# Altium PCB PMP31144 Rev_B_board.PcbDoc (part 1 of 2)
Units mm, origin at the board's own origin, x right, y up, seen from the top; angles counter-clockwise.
Board outline 104.14 x 73.15 mm, 4 copper layers (Top Layer, Layer 1, Layer 2, Bottom Layer), stack 1.787 mm thick; 110 components, 51 nets, 277 pads, 139 vias.
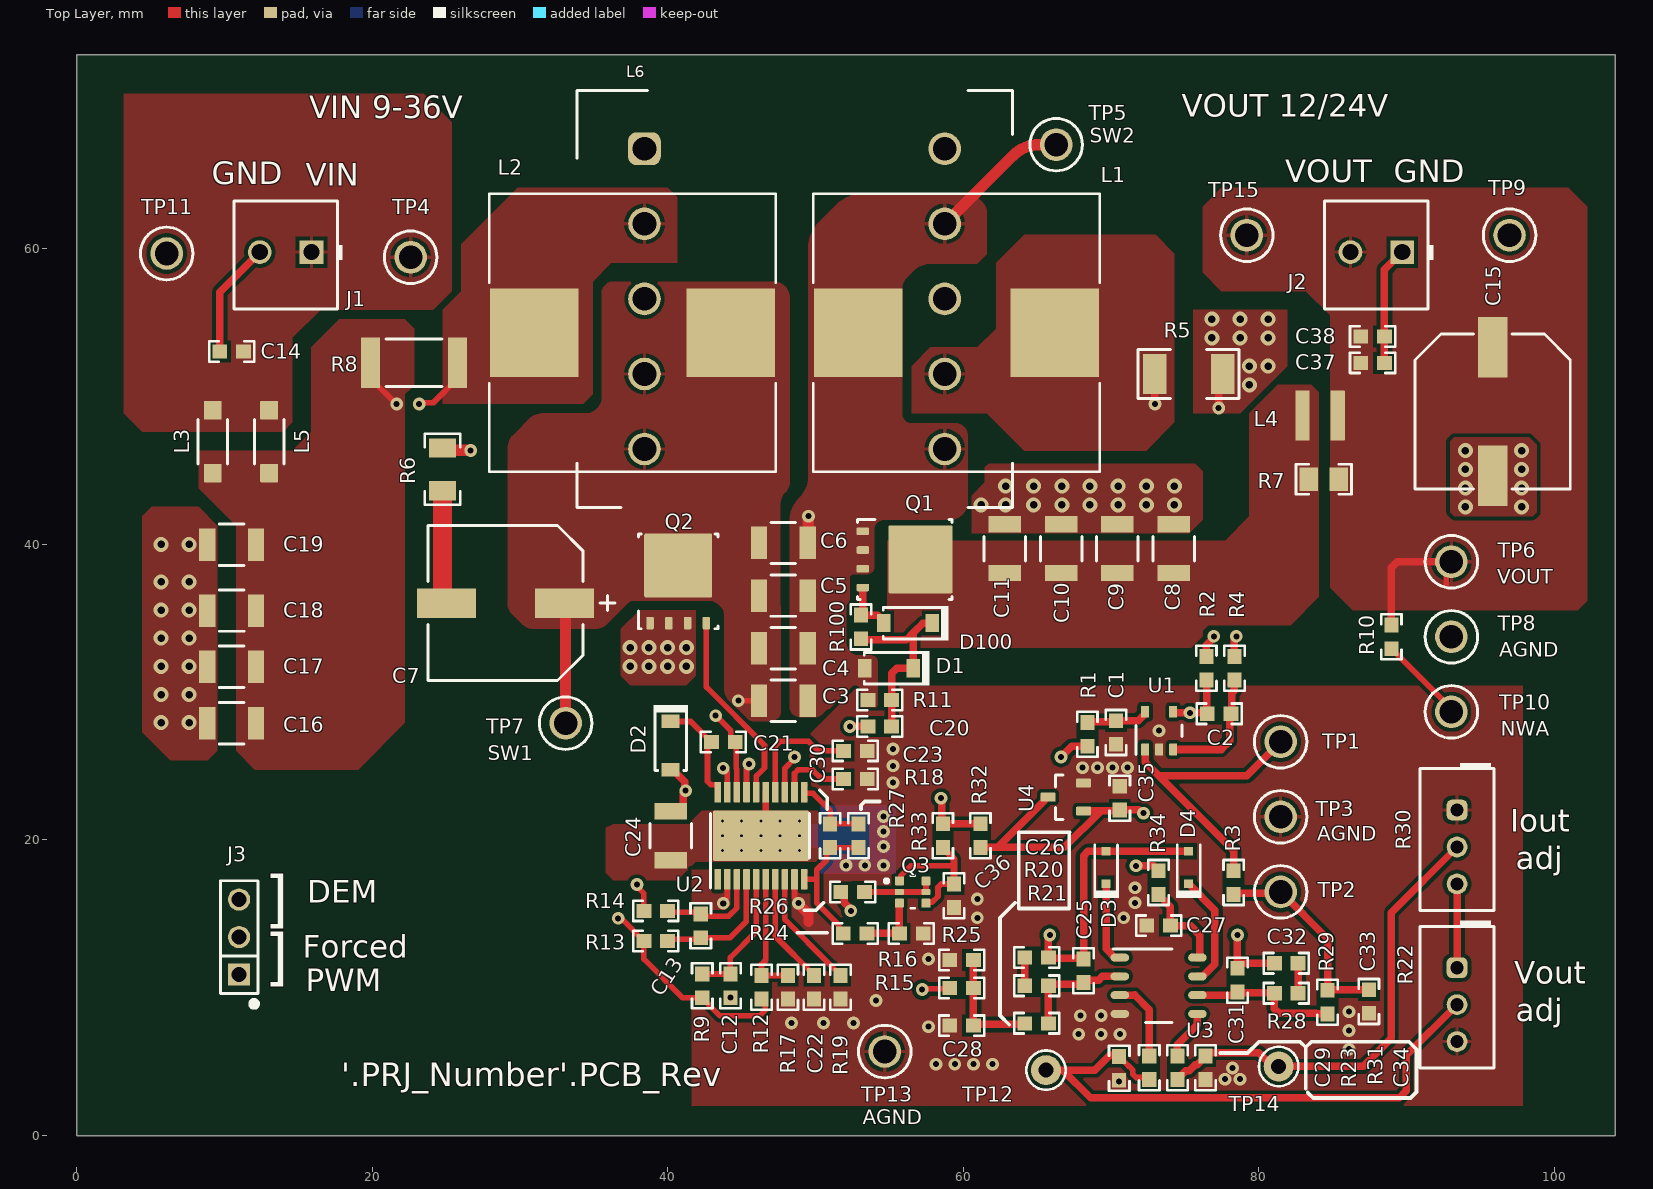
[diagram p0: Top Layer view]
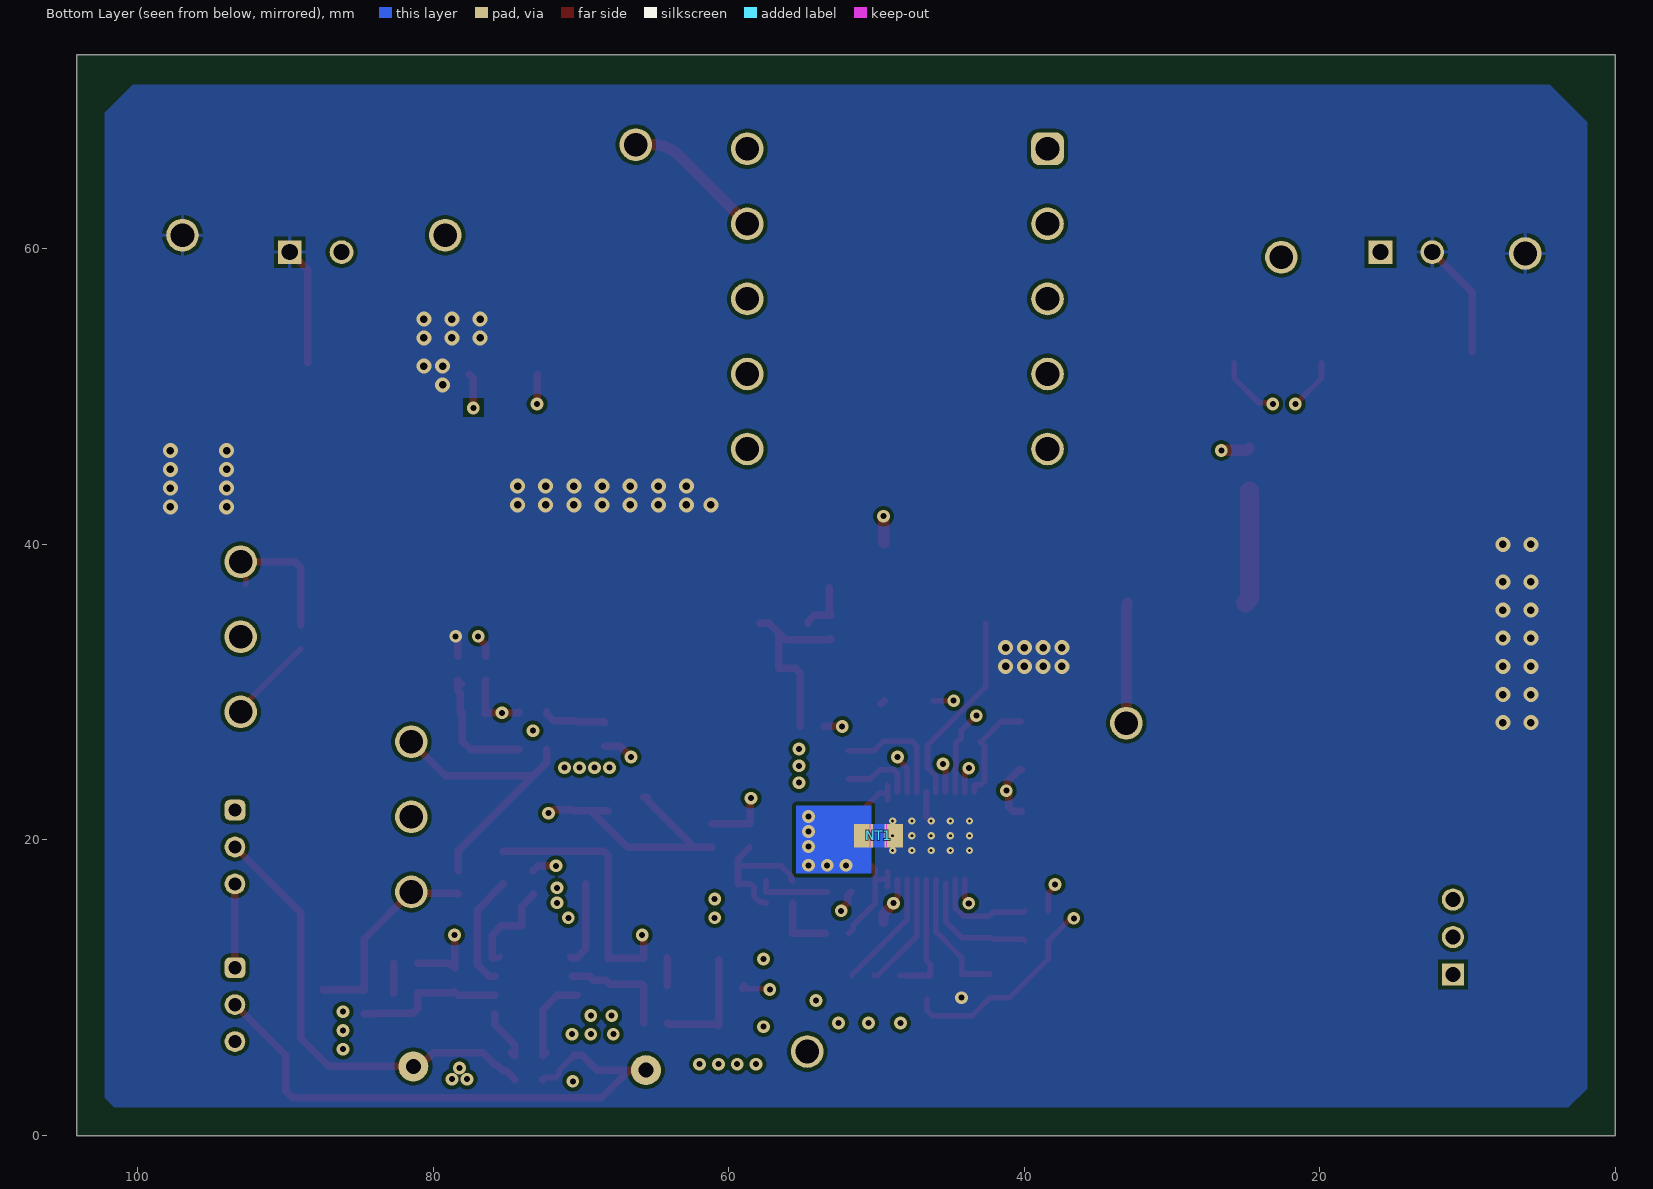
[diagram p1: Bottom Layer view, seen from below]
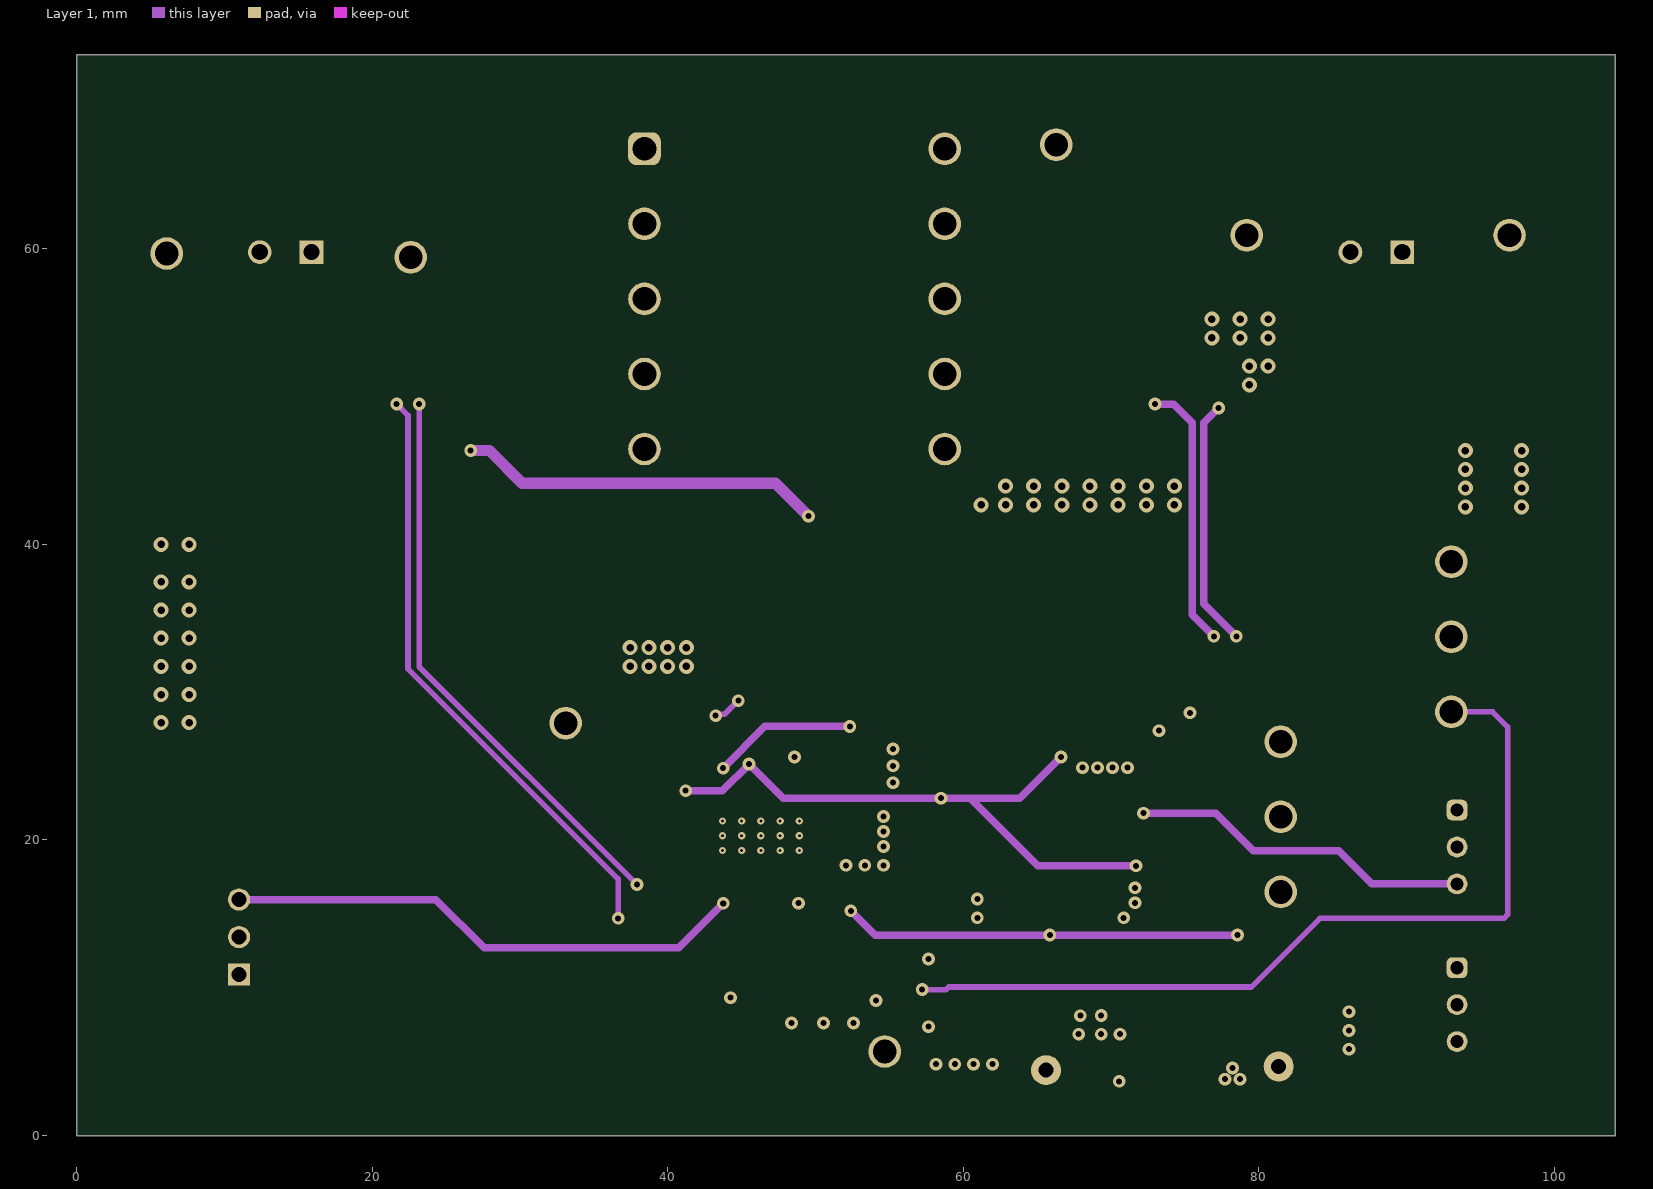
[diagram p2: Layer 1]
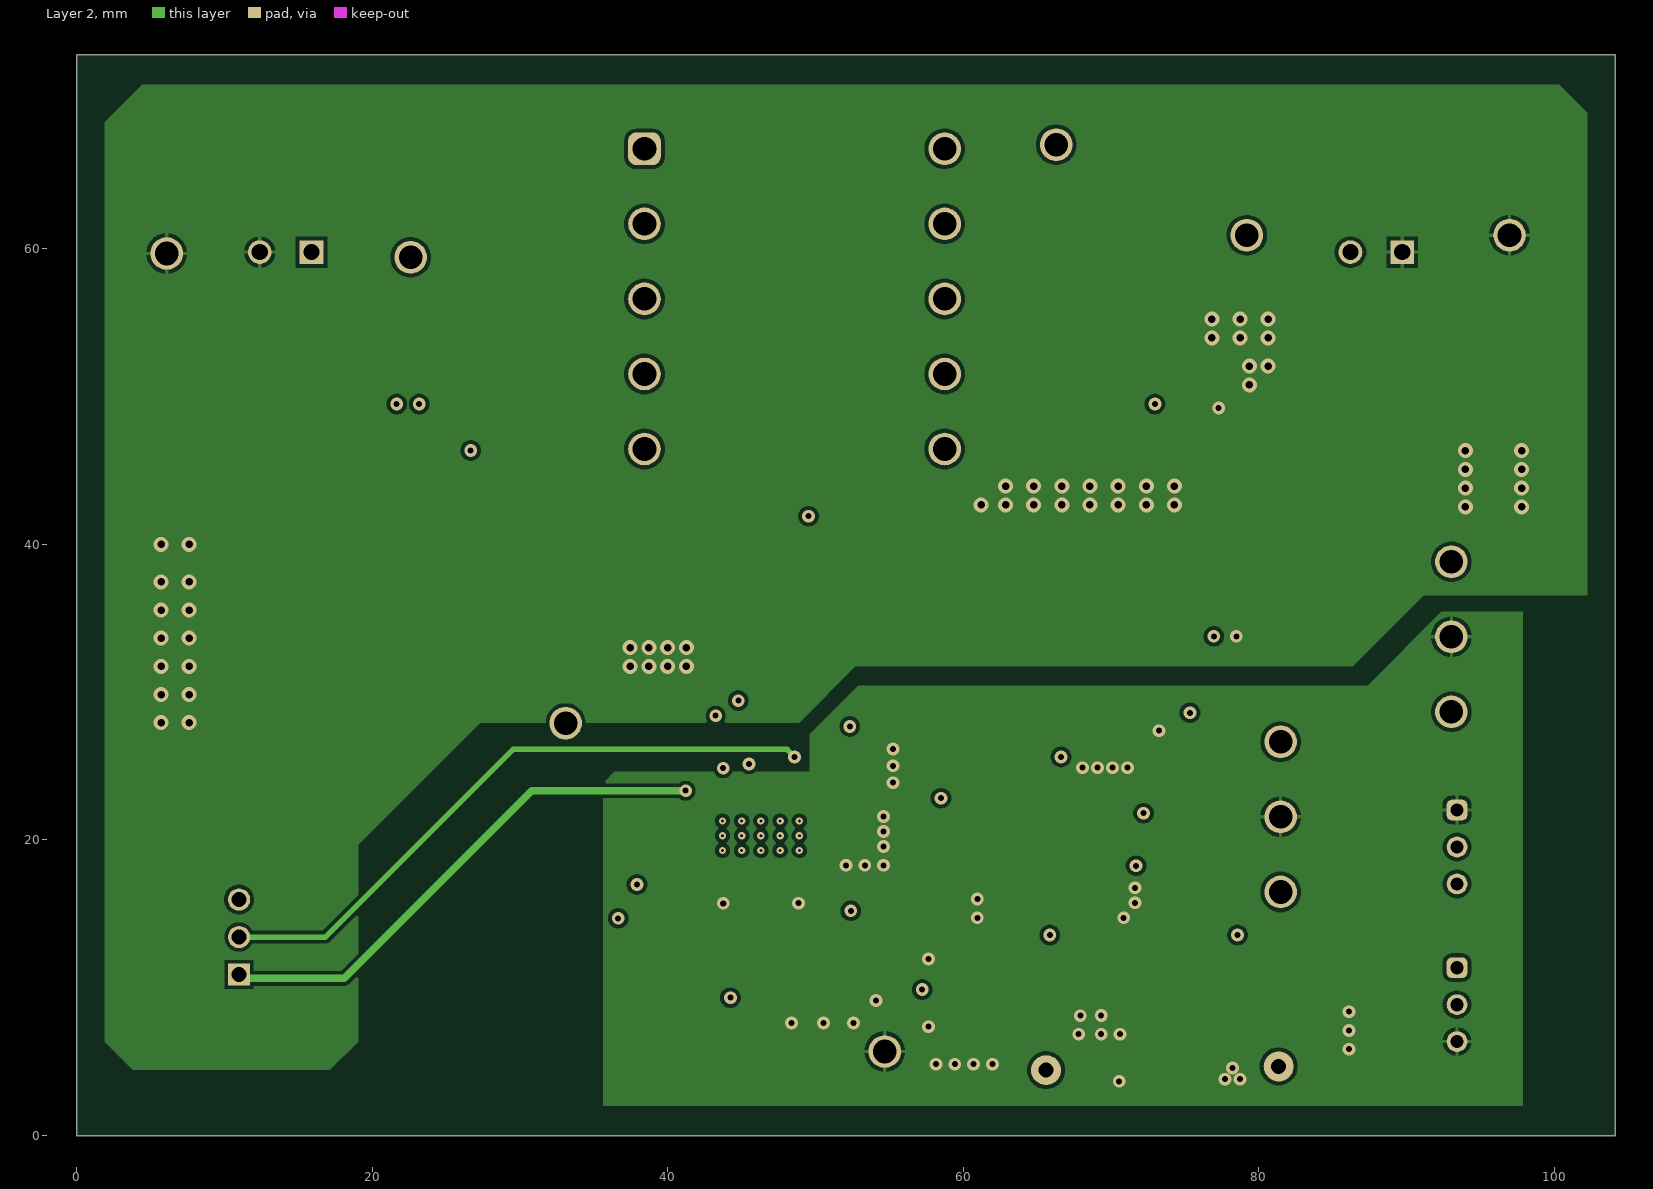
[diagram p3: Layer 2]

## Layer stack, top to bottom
Top Solder: solder mask 0.0102, Solder Resist, Dk 3.5
Top Layer: signal copper 0.0356
Dielectric 1: prepreg 0.0711, PP-006, Dk 4.1
Layer 1: signal copper 0.035
Dielectric1: core 1.5037, FR-4, Dk 4.8
Layer 2: signal copper 0.035
Dielectric 2: prepreg 0.0711, PP-006, Dk 4.1
Bottom Layer: signal copper 0.0356
Bottom Solder: solder mask 0.0102, Solder Resist, Dk 3.5

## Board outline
0,0 0,73.152 104.14,73.152 104.14,0

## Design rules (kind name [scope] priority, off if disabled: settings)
AcuteAngle [All] p1: minimum=4.50000000000000E+0001 checktracksonly=FALSE
AssemblyTestPointUsage [All] p1: valid=2
BoardOutlineClearance BoardOutlineClearance_MountingHoles [OnCopper and InComponentClass('Mounting Holes')] p1: gap=1.016 ignorepadtopadclearanceinfootprint=FALSE
BoardOutlineClearance BoardOutlineClearance_Poly [OnCopper and IsPoly] p2: gap=0.635 ignorepadtopadclearanceinfootprint=FALSE
BoardOutlineClearance [OnCopper and Not InComponentClass('Logo') and not InComponentClass('FiducialMark') and not InRegion(1000,500,4000,800) and not InPoly] p3: gap=1.905 ignorepadtopadclearanceinfootprint=FALSE
Clearance Clearance_1 [InComponent('NT1')] p1: gap=0 ignorepadtopadclearanceinfootprint=FALSE
Clearance Clearance_Keepouts [((IsTrack Or IsArc) And Not InPoly) And IsFree and IsKeepOut vs ((IsTrack Or IsArc) And Not InPoly) And IsFree and IsKeepOut] p2: gap=0 ignorepadtopadclearanceinfootprint=FALSE
Clearance Clearance_Poly [InPolygon] p3: gap=0.254 ignorepadtopadclearanceinfootprint=FALSE
Clearance Clearance_FiducialMark [IsKeepOut and InComponentClass('FiducialMark') vs IsPad and InComponentClass('FiducialMark')] p4: gap=0 ignorepadtopadclearanceinfootprint=FALSE
Clearance Clearance_U2 [InComponent('U2')] p5: gap=0.254 ignorepadtopadclearanceinfootprint=FALSE except(0.2: Arc-SMDPad Track-SMDPad SMDPad-SMDPad)
Clearance [All] p6: gap=0.254 ignorepadtopadclearanceinfootprint=FALSE
ComponentClearance ComponentClearance_MountingHoles_FiducialMarks [InComponentClass('Mounting Holes') vs InComponentClass('FiducialMark')] p1: gap=1.27 collisioncheckmode=3 verticalgap=0.254 showdistances=FALSE
ComponentClearance ComponentClearance_Shunt [InComponentClass('Header') vs InComponentClass('Shunt')] p2: gap=0 collisioncheckmode=3 verticalgap=0 showdistances=FALSE
ComponentClearance ComponentClearance_Logo [InComponentClass('Logo')] p3: gap=1.27 collisioncheckmode=3 verticalgap=0.254 showdistances=FALSE
ComponentClearance ComponentClearance_ScrewToNut [(HasFootprint('NY PMS 440 0025 PH')) vs (HasFootprint('Keystone_1902C'))] p4: gap=0.127 collisioncheckmode=3 verticalgap=0.254 showdistances=FALSE
ComponentClearance ComponentClearance_MountingHoles [InComponentClass('Mounting Holes')] p5: gap=6.35 collisioncheckmode=3 verticalgap=2540 showdistances=FALSE
ComponentClearance ComponentClearance_SmallPassives [HasFootprint('0201*') or HasFootprint('0402*') or HasFootprint('0508') or HasFootprint('0603*') or HasFootprint('0612') or HasFootprint('0805*') or HasFootprint('0815*') or HasFootprint('0830*') or HasFootprint('1206*') or HasFootprint('1210*') or HasFootprint('1808*') or HasFootprint('1812*') or HasFootprint('1825*') or HasFootprint('2010*') or HasFootprint('2220*') or HasFootprint('2225*') or HasFootprint('2512*') or HasFootprint('2728*') or HasFootprint('3518*') vs HasFootprint('0201*') or HasFootprint('0402*') or HasFootprint('0508') or HasFootprint('0603*') or HasFootprint('0612') or HasFootprint('0805*') or HasFootprint('0815*') or HasFootprint('0830*') or HasFootprint('1206*') or HasFootprint('1210*') or HasFootprint('1808*') or HasFootprint('1812*') or HasFootprint('1825*') or HasFootprint('2010*') or HasFootprint('2220*') or HasFootprint('2225*') or HasFootprint('2512*') or HasFootprint('2728*') or HasFootprint('3518*')] p6: gap=0.38 collisioncheckmode=3 verticalgap=0.254 showdistances=FALSE
ComponentClearance ComponentClearance_1 [InComponent('L1')or InComponent('L2') vs InComponent('L6')] p7: gap=0 collisioncheckmode=3 verticalgap=0 showdistances=FALSE
ComponentClearance ComponentClearance_THtoSMT [IsThruComponent vs IsSMTComponent] p8: gap=1.016 collisioncheckmode=3 verticalgap=0.762 showdistances=FALSE
ComponentClearance ComponentClearance_THtoTH [IsThruComponent vs IsThruComponent] p9: gap=0.762 collisioncheckmode=3 verticalgap=0.762 showdistances=FALSE
ComponentClearance [All] p10: gap=0.762 collisioncheckmode=3 verticalgap=0.254 showdistances=FALSE
DiffPairsRouting [All] p1: maxlimit=2.54 minlimit=0.254 mostfreqgap=0.254 toplayer_minwidth=0.381 toplayer_maxwidth=0.381 toplayer_prefwidth=0.381 midlayer1_minwidth=0.381 midlayer1_maxwidth=0.381 midlayer1_prefwidth=0.381 midlayer2_minwidth=0.381 midlayer2_maxwidth=0.381 midlayer2_prefwidth=0.381 bottomlayer_minwidth=0.381 bottomlayer_maxwidth=0.381 bottomlayer_prefwidth=0.381 maxuncoupledlength=25.4
FabricationTestPointUsage TestPointUsage [All] p1: valid=2 allowmultiple=FALSE
FabricationTestpoint Testpoint [All] p1: side=3 testpointundercomponent=TRUE minsize=1.016 maxsize=2.54 preferedsize=1.524 minholesize=0 maxholesize=1.016 preferedholesize=0.813 testpointgrid=0.025 allowsidetop=TRUE allowsidebottom=TRUE usegrid=TRUE gridtolerance=0
FanoutControl Fanout_LCC [IsLCC] p1: bgadir=Out bgaviamode=Centered fanoutstyle=Auto fanoutdirection=Alternating viagrid=0.025 // Fanout_LCC (Default Rule)
FanoutControl Fanout_BGA [IsBGA] p2: bgadir=Out bgaviamode=Centered fanoutstyle=Auto fanoutdirection=Alternating viagrid=0.025 // Fanout_BGA (Default Rule)
FanoutControl Fanout_Default [All] p4: bgadir=Out bgaviamode=Centered fanoutstyle=Auto fanoutdirection=Alternating viagrid=0.025 // Fanout_Default (Default Rule)
FanoutControl Fanout_Small [(CompPinCount < 5)] p5: bgadir=Out bgaviamode=Centered fanoutstyle=Auto fanoutdirection=OutThenIn viagrid=0.025 // Fanout_Small (Default Rule)
HoleSize [All] p1: absolutevalues=TRUE maxlimit=6.375 minlimit=0.2 maxpercent=80.000 minpercent=20.000
MinimumAnnularRing MinimumAnnularRing_ThermalPadVias [IsVia and InAnyComponent] p1: minimumring=0.15
MinimumAnnularRing [All] p2: minimumring=0.203
MinimumSolderMaskSliver MinimumSolderMaskSliver_Logo [InComponentClass('Logo') vs InComponentClass('Logo')] p1: minsoldermaskwidth=0.018
MinimumSolderMaskSliver [All] p2: minsoldermaskwidth=0.1
PlaneConnect [All] p1: planeconnectstyle=Relief reliefexpansion=0.254 reliefentries=4 reliefconductorwidth=0.254 reliefairgap=0.254
PolygonConnect [All] p1: thpad.connectstyle=Relief thpad.reliefconductorwidth=0.254 thpad.reliefentries=4 thpad.polygonreliefangle="90 Angle" thpad.airgapwidth=0.254 smdpad.connectstyle=Direct smdpad.reliefconductorwidth=0.254 smdpad.reliefentries=4 smdpad.polygonreliefangle="90 Angle" smdpad.airgapwidth=0.254 via.connectstyle=Direct via.reliefconductorwidth=0.254 via.reliefentries=4 via.polygonreliefangle="90 Angle" via.airgapwidth=0.254
RoutingVias ThermalPadVias [IsVia and InAnyComponent] p1: holewidth=0.2 width=0.5 viastyle="Through Hole" minholewidth=0.2 minwidth=0.5 maxholewidth=0.33 maxwidth=0.6
RoutingVias [All] p2: holewidth=0.406 width=0.864 viastyle="Through Hole" minholewidth=0.2 minwidth=0.66 maxholewidth=1.016 maxwidth=1.651
SilkToBoardRegionClearance [Not ((IsComment or IsDesignator) And (Hide <> 'False')) and not InRegion(1000,500,4000,800)] p1:
SilkToSilkClearance SilkToSilkClearance_Pb-FreeLogo [(HasFootprint('Pb-Free_Overlay_Medium') OR HasFootprint('Pb-Free_Overlay_Small')) vs (HasFootprint('Pb-Free_Overlay_Medium') OR HasFootprint('Pb-Free_Overlay_Small'))] p1: silktosilkclearance=0
SilkToSilkClearance [All] p2: silktosilkclearance=0.102
SilkToSolderMaskClearance SilkToComponentPadClearance [(IsPad or IsFill or IsRegion) and InAnycomponent] p1: minsilkscreentomaskgap=0.127 clearancetoexposedcopper=TRUE
SilkToSolderMaskClearance "Silk to Solder Mask Opening" [All] p2: minsilkscreentomaskgap=0.102 clearancetoexposedcopper=FALSE
SolderMaskExpansion [All] p1: expansion=0.05 istentingtop=FALSE
Width [All] p1: maxlimit=2.54 minlimit=0.152 preferedwidth=0.254 checkconnectedcopper=TRUE
15 further rules are at their usual default settings.

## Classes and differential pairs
component class Header: J3

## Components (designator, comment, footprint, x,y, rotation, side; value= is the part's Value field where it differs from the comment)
C1 "C1608X7R1H104K080AA" 0603 70.339,27.272 r270 top value=0.1uF
C2 "GRM188R71H224KAC4D" 0603 77.324,28.542 r0 top value=0.22uF
C3 "C3225X7R1H106M250AC" 1210_280 47.827,29.431 r180 top value=10uF
C4 "C3225X7R1H106M250AC" 1210_280 47.827,32.987 r180 top value=10uF
C5 "C3225X7R1H106M250AC" 1210_280 47.827,36.543 r180 top value=10uF
C6 "C3225X7R1H106M250AC" 1210_280 47.827,40.099 r180 top value=10uF
C7 "PCR1H181MCL1GS" CR_1000x1270 29.031,36.035 r180 top value=180uF
C8 "C3225X7R1H106M250AC" 1210_280 74.246,39.718 r90 top value=10uF
C9 "C3225X7R1H106M250AC" 1210_280 70.436,39.718 r90 top value=10uF
C10 "C3225X7R1H106M250AC" 1210_280 66.626,39.718 r90 top value=10uF
C11 "C3225X7R1H106M250AC" 1210_280 62.816,39.718 r90 top value=10uF
C12 "CGA3E3X7R1H474K080AE" 0603 44.246,10.127 r270 top value=0.47uF
C13 "885012206083" 0603 42.239,14.191 r90 top value=1000pF
C14 "C1608X7R1H104K080AA" 0603 10.489,53.053 r180 top value=0.1uF
C15 "EEEFK1V331P" Panasonic_G 95.833,48.989 r270 top value=330uF
C16 "C3225X7R1H106M250AC" 1210_280 10.489,27.907 r180 top value=10uF
C17 "C3225X7R1H106M250AC" 1210_280 10.489,31.717 r180 top value=10uF
C18 "C3225X7R1H106M250AC" 1210_280 10.489,35.527 r180 top value=10uF
C19 "C3225X7R1H106M250AC" 1210_280 10.489,39.972 r180 top value=10uF
C20 "C1608X5R1H105K080AB" 0603 54.356,27.686 r180 top value=1uF
C21 "CGA3E3X7R1H474K080AE" 0603 43.771,26.637 r180 top value=0.47uF
C22 "C0603C104J5RACTU" 0603 49.911,10.033 r270 top value=0.1uF
C23 "C0603C334K4RACTU" 0603 52.705,26.035 r0 top value=0.33uF
C24 "C3225X7R1H106M250AC" 1210_280 40.207,20.287 r90 top value=10uF
C25 "GRM1885C1H151JA01D" 0603 68.147,11.151 r90 top value=150pF
C26 "C0603C104K5RACAUTO" 0603 64.972,12.04 r180 top value=0.1uF
C27 "C0603C104K5RACAUTO" 0603 73.227,14.199 r0 top value=0.1uF
C28 "885012206083" 0603 59.892,7.435 r180 top value=1000pF
C29 "GRM188R71E105KA12D" 0603 70.56,4.547 r270 top value=1uF
C30 "GRM1885C1H151JA01D" 0603 51.002,20.287 r90 top value=150pF
C31 "DNP" 0603 78.561,10.516 r90 top
C32 "C0603C333J3RACTU" 0603 81.863,11.659 r0 top value=0.033uF
C33 "GRM1885C1H100JA01D" 0603 87.451,9.068 r270 top value=10pF
C34 "GRM188R71E105KA12D" 0603 76.402,4.585 r270 top value=1uF
C35 "C0603C104K5RACAUTO" 0603 70.597,22.835 r90 top value=0.1uF
C36 "C0603C104K5RACAUTO" 0603 59.377,16.223 r90 top value=0.1uF
C37 "C1608X5R1H105K080AB" 0603 87.705,52.291 r0 top value=1uF
C38 "C1608X7R1H104K080AA" 0603 87.705,54.069 r0 top value=0.1uF
D1 "MBR1H100SFT3G" SOD-123FL 54.991,31.623 r180 top value=100V
D2 "MBR1H100SFT3G" SOD-123FL 40.207,26.383 r270 top value=100V
D3 "BAT54HT1G" SOD-323 69.671,18.136 r90 top value=30V
D4 "BAT54HT1G" SOD-323 75.259,18.136 r90 top value=30V
D100 "MBR1H100SFT3G" SOD-123FL 56.261,34.671 r180 top value=100V
J1 "39357-0002" MOLEX_39357-0002 14.144,59.784 r180 top
J2 "39357-0002" MOLEX_39357-0002 87.959,59.784 r180 top
J3 "PEC03SAAN" CONN_PEC03SAAN 10.997,13.429 r90 top
L1 "74435574700" WE-HCB_1890 59.557,54.323 r180 top value=47uH
L2 "74435574700" WE-HCB_1890 37.621,54.323 r0 top value=47uH
L3 "742792410" 1806_HighSpeed 9.219,46.957 r270 top value="60 ohm"
L4 "XGL4020-471MEC" FP-XGL4020-471MEC_SMT_4MM0_4MM0-MFG 84.149,48.735 r0 top
L5 "742792410" 1806_HighSpeed 13.029,46.957 r270 top value="60 ohm"
L6 "" Wurth_750343473 48.59,56.617 r0 top
NT1 "Net-Tie" Net-Tie_0805_HV_NoOverlay 49.861,20.287 r180 bottom net-tie
Q1 "CSD19502Q5B" DNK0008A 56.033,38.989 r0 top value=80V
Q2 "CSD19502Q5B" DNK0008A 40.715,37.495 r90 top value=80V
Q3 "BCM857BS,115" FP-BCM857BS,115_TSSOP6-MFG 56.583,16.477 r0 top value=-45V
R1 "CRCW060310R0JNEAHP" 0603 68.401,27.145 r270 top value=10
R2 "RT0603DRE0710RL" 0603 76.454,31.623 r270 top value=10.0
R3 "CRCW060349R9FKEA" 0603 78.307,17.12 r90 top value=49.9
R4 "RT0603DRE0710RL" 0603 78.359,31.623 r270 top value=10.0
R5 "CSRN2010FK25L0" 2010 75.259,51.529 r180 top value=0.025
R6 "CRCW12063R24FKEA" 1206 24.765,45.085 r90 top value=3.24
R7 "RC0805FR-074R7L" 0805_HV 84.403,44.417 r0 top value=4.70
R8 "KRL3264-C-R007-G-T1" 2512 22.837,52.291 r180 top value=0.007
R9 "CRCW06033R30JNEA" 0603 42.341,10.127 r270 top value=3.3
R10 "CRCW060349R9FKEA" 0603 88.975,33.749 r270 top value=49.9
R11 "RT0603DRD071KL" 0603 54.356,29.464 r0 top value=1.00k
R12 "RC0603FR-07100KL" 0603 46.355,10.033 r270 top value=100k
R13 "ERJ-3EKF1000V" 0603 39.191,13.175 r180 top value=100
R14 "ERJ-3EKF1000V" 0603 39.191,15.207 r180 top value=100
R15 "CRCW060390K9FKEA" 0603 59.892,9.975 r180 top value=90.9k
R16 "CRCW060310K5FKEA" 0603 59.892,11.88 r0 top value=10.5k
R17 "RC0603FR-0716K5L" 0603 48.133,10.033 r90 top value=16.5k
R18 "RC0603FR-07147KL" 0603 52.705,24.13 r180 top value=147k
R19 "CRCW060388K7FKEA" 0603 51.689,10.033 r90 top value=88.7k
R20 "RC0603FR-0768KL" 0603 64.972,10.135 r180 top value=68.0k
R21 "CRCW060310K0FKEA" 0603 64.972,7.595 r0 top value=10.0k
R22 "PV36W104C01B00" Bourns_PV36W 93.42,8.857 r270 top value=100k
R23 "CRCW060310K0FKEA" 0603 72.592,4.585 r90 top value=10.0k
R24 "M55342K12B10E0T" 0603 52.686,13.683 r180 top value=10.0k
R25 "RC0603FR-071KL" 0603 56.496,13.683 r180 top value=1.00k
R26 "RC0603FR-072K2L" 0603 52.519,16.477 r0 top value=2.20k
R27 "RC0603FR-0720KL" 0603 52.907,20.287 r270 top value=20.0k
R28 "CRCW06030000Z0EA" 0603 81.863,9.627 r0 top value=0
R29 "CRCW060310K0FKEA" 0603 84.657,9.03 r270 top value=10.0k
R30 "PV36W104C01B00" Bourns_PV36W 93.42,19.525 r270 top value=100k
R31 "CRCW060310K0FKEA" 0603 74.497,4.585 r90 top value=10.0k
R32 "CRCW06038K25FKEA" 0603 61.162,20.295 r90 top value=8.25k
R33 "RT0603DRE0710RL" 0603 58.622,20.295 r90 top value=10.0
R34 "RT0603DRE0710RL" 0603 73.227,17.12 r270 top value=10.0
R100 "RT0603DRE0710RL" 0603 53.086,34.417 r90 top value=10.0
TP1 "5010" Keystone5010 81.482,26.645 r0 top
TP2 "5014" Keystone5014 81.482,16.485 r0 top
TP3 "5011" Keystone5011 81.482,21.565 r90 top
TP4 "5010" Keystone5010 22.606,59.436 r90 top
TP5 "5014" Keystone5014 66.294,67.056 r180 top
TP6 "5010" Keystone5010 93.039,38.829 r90 top
TP7 "5010" Keystone5010 33.095,27.907 r0 top
TP8 "5011" Keystone5011 93.039,33.749 r180 top
TP9 "5011" Keystone5011 96.976,60.927 r90 top
TP10 "5014" Keystone5014 93.039,28.669 r90 top
TP11 "5011" Keystone5011 6.096,59.69 r270 top
TP12 "5000" Keystone5000 65.607,4.42 r90 top
TP13 "5011" Keystone5011 54.693,5.682 r90 top
TP14 "5000" Keystone5000 81.355,4.674 r90 top
TP15 "5010" Keystone5010 79.196,60.927 r90 top
U1 "INA293A2IDBVR" DBV0005A_L 73.26,27.399 r90 top
U2 "LM5122MHX/NOPB" PWP0020A_N 46.311,20.287 r90 top
U3 "TLC272AID" D0008A_L 73.227,10.135 r0 top
U4 "LM4040D30IDBZR" DBZ0003A_N 66.947,22.901 r180 top value=LM4040D30

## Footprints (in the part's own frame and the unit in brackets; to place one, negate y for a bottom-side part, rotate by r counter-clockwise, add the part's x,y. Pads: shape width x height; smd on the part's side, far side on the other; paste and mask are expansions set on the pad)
0603 [mm] "0603 from SM-752 data"
  rect 1x0.95 smd: 1(-0.8,0) 2(0.8,0)
  silkscreen extent -1.52,-0.69 1.52,0.69, body extent -0.87,-0.47 0.87,0.47, height 1
0805_HV [mil] "0805 with 30mil clearance between pads"
  rect 50x63 smd: 1(-40,0) 2(40,0)
  silkscreen extent -74,-40 74,40, body extent -43,-29 43,29, height 57
1206 [mm] "1206 from SM-752 data"
  rect 1.3x1.85 smd: 1(-1.45,0) 2(1.45,0)
  silkscreen extent -2.4,-1.21 2.4,1.21, body extent -1.7,-0.9 1.7,0.9, height 1.35
1210_280 [mm] "SMD, 2-Leads, Body 3.6x2.8mm, Height 2.8mm"
  rect 1.1x2.2 smd: 1(-1.65,0) 2(1.65,0)
  silkscreen extent -0.84,-1.4 0.84,1.4, body extent -1.8,-1.4 1.8,1.4, height 2.8
1806_HighSpeed [mm] "Wurth recommended land pattern"
  rrect8% 1.25x1.2 smd: 1(-2.125,0) 2(2.125,0)
  silkscreen extent -1.5,-1 1.5,1, body extent -2.25,-0.8 2.25,0.8, height 1.61
2010 [mm] "Chip Capacitor, Body 5.08x2.54mm, IPC Medium Density"
  rect 1.6x2.7 smd: 1(-2.3,0) 2(2.3,0)
  silkscreen extent -3.42,-1.65 3.42,1.65, body extent -2.73,-1.45 2.73,1.45, height 1.66
2512 [mm] "Chip Resistor, Body 6.3x3.2mm, IPC Medium Density"
  rect 1.3x3.4 smd: 1(-2.95,0) 2(2.95,0)
  silkscreen extent -1.9,-1.6 1.9,1.6, body extent -3.22,-1.67 3.22,1.67, height 0.71
Bourns_PV36W [mm] "TH, 3-Leads, Body 9.53x4.83mm, Pitch 2.5mm"
  rrect50% 1.4x1.4 hole 0.9: 1(-2.5,0)
  round 1.4 hole 0.9: 2(0,0) 3(2.5,0)
  silkscreen extent -5.7,-2.5 4.3,2.5, body extent -5.29,-2.49 4.31,2.51, height 11.53
CONN_PEC03SAAN [mm] "SULLINS"
  rect 1.5x1.5 hole 1.016: 1(-2.54,0)
  round 1.5 hole 1.016: 2(0,0) 3(2.54,0)
  silkscreen extent -4.72,-1.27 3.81,1.27, body extent -3.84,-1.3 3.84,1.3, height 8.38
CR_1000x1270 [mm] "SMD, 2-Leads, Dia 10.5mm, Pin Spacing 8mm"
  rect 4x2 smd: 1(-4,0) 2(4,0)
  silkscreen extent -7.4,-5.25 5.25,5.25, body extent -5.25,-5.25 5.25,5.25, height 12.71
D0008A_L [mm] "SOIC, 8-Leads, Body 4.9x3.9mm, Pitch 1.27mm, IPC High Density"
  oval 1.25x0.55 smd: 1(-2.625,1.905) 2(-2.625,0.635) 3(-2.625,-0.635) 4(-2.625,-1.905) 5(2.625,-1.905) 6(2.625,-0.635) 7(2.625,0.635) 8(2.625,1.905)
  silkscreen extent -3.1,-2.5 0.9,2.5, body extent -3,-2.45 3,2.45, height 1.63
DBV0005A_L [mm] "SOT23, 5-Leads, Body 2.9x1.6mm, Pitch 0.95mm, Lead Span 2.8mm, IPC High Density"
  rrect18% 0.8x0.55 smd: 1(-1.275,0.95) 2(-1.275,0) 3(-1.275,-0.95) 4(1.275,-0.95) 5(1.275,0.95)
  silkscreen extent -1.63,-1.55 0.38,1.55, body extent -1.42,-1.46 1.42,1.46, height 1.09
DBZ0003A_N [mm] "SOT23, 3-Leads, Body 2.9x1.3mm, Pitch 0.95mm, Lead Span 2.4mm, IPC Medium Density"
  rrect17% 1x0.6 smd: 1(-1.2,0.95) 2(-1.2,-0.95) 3(1.2,0)
  silkscreen extent 0.2,-1.5 0.7,1.5, body extent -1.26,-1.46 1.26,1.46, height 0.98
DNK0008A [mm] "SON, 8-Leads, Body 5x6mm"
  rrect39% 0.86x0.51 smd paste-0.05 mask-0.05: 1(-2.82,1.905) 2(-2.82,0.635) 3(-2.82,-0.635) 4(-2.82,-1.905) 5(2.82,-1.905) 6(2.82,-0.635) 7(2.82,0.635) 8(2.82,1.905)
  rrect8% 1.48x1.27 on Top Paste: 9(-0.18,-1.47) 9(-0.18,0) 9(-0.18,1.47) 9(1.5,-1.47) 9(1.5,0) 9(1.5,1.47)
  rrect5% 4.34x4.6 smd paste-3 mask-0.05: 9(1.08,0)
  silkscreen extent -3.2,-2.7 3.2,2.7, body extent -3.05,-2.55 3.05,2.55, height 1.06
FP-BCM857BS,115_TSSOP6-MFG [mm]
  rrect17% 0.6x0.6 smd paste-1000 mask+0: 1(-0.9,0.75) 3(-0.9,-0.75) 4(0.9,-0.75) 6(0.9,0.75)
  rrect25% 0.6x0.4 smd paste+0 mask+0: 2(-0.9,0) 5(0.9,0)
  silkscreen extent -1.9,-1.1 0.15,1.1, body extent -1.33,-1.2 1.33,1.2, height 0.25
FP-XGL4020-471MEC_SMT_4MM0_4MM0-MFG [mm]
  rrect10% 0.98x3.4 smd paste+0 mask+0: 1(-1.185,0) 2(1.185,0)
  body extent -2.25,-2.25 2.25,2.25, height 0.25
Keystone5000 [mil] "For Keystone 500x miniature loop terminals"
  round 80 hole 40: 1(0,0)
  silkscreen extent -52,-52 52,52, body extent -49,-49 49,49, height 182
Keystone5010 [mil] "Keystone Multipurpose loops"
  round 87 hole 63: 1(0,0)
  silkscreen extent -70,-70 70,70, body extent -63,-63 63,62, height 319
Keystone5011 [mil] "Keystone Multipurpose loops"
  round 87 hole 63: 1(0,0)
  silkscreen extent -70,-70 70,70, body extent -63,-63 63,62, height 319
Keystone5014 [mil] "Keystone Multipurpose loops"
  round 87 hole 63: 1(0,0)
  silkscreen extent -70,-70 70,70, body extent -63,-63 63,62, height 319
MOLEX_39357-0002 [mm] "Terminal Block, 3.5 mm, 2x1, TH"
  rect 1.6x1.6 hole 1.1: 1(-1.75,0)
  round 1.6 hole 1.1: 2(1.75,0)
  silkscreen extent -3.86,-3.45 3.5,3.84, body extent -3.55,-3.45 3.56,3.84, height 8.51
Net-Tie_0805_HV_NoOverlay [mil] "0805_HV pads tied by 10mil copper trace which can be cut.  An 0805 part can be placed on pads."
  rect 50x63 smd paste-25: 1(-40,0) 2(40,0)
  Top Layer lines w61.81: 16,0 -16,0
  Top Layer keep-out lines w1: 22,-30.91 22,30.91 ; -22,-30.91 -22,30.91
Panasonic_G [mm] "SMD, 2-Leads, Dia 10mm"
  rect 4.1x2 smd: 1(-4.35,0) 2(4.35,0)
  silkscreen extent -5.25,-5.25 5.25,5.25, body extent -5.25,-5.25 5.25,5.25, height 10.51
PWP0020A_N [mm] "TSOP, 20-Leads, Body 6.5x4.4mm, Pitch 0.65mm, Exposed Pad, IPC Medium Density"
  rrect22% 1.4x0.45 smd: 1(-2.95,2.925) 2(-2.95,2.275) 3(-2.95,1.625) 4(-2.95,0.975) 5(-2.95,0.325) 6(-2.95,-0.325) 7(-2.95,-0.975) 8(-2.95,-1.625) 9(-2.95,-2.275) 10(-2.95,-2.925) 11(2.95,-2.925) 12(2.95,-2.275) 13(2.95,-1.625) 14(2.95,-0.975) 15(2.95,-0.325) 16(2.95,0.325) 17(2.95,0.975) 18(2.95,1.625) 19(2.95,2.275) 20(2.95,2.925)
  rrect6% 3.4x6.5 smd paste-2 mask-2: 21(0,0)
  rrect3% 3.15x4.35 on Top Paste: 21(0,0)
  rrect3% 3.15x4.35 on Top Solder: 21(0,0)
  silkscreen extent -3.55,-3.3 1.5,3.4, body extent -3.21,-3.25 3.21,3.25, height 1
SOD-123FL [mm] "Copied from SOD-123"
  rect 0.915x1.22 smd: 1(-1.637,0) 2(1.637,0)
  silkscreen extent -2.74,-1.16 1.68,1.16, body extent -1.9,-0.9 1.9,0.9, height 1
SOD-323 [mm] "NXP recommended land pattern"
  rect 0.6x0.6 smd paste-0.05: 1(-1.1,0) 2(1.1,0)
  silkscreen extent -2.06,-0.86 1.53,0.86, body extent -1.3,-0.67 1.3,0.68, height 1.1
WE-HCB_1890 [mm] "WURTH ELEKTRONIK"
  rect 6x6 smd: 1(-6.65,0) 2(6.65,0)
  silkscreen extent -9.7,-9.4 9.7,9.4, body extent -9.65,-9.35 9.65,9.35, height 9.2
Wurth_750343473 [mm] "TH, 10-Leads, Body 29.21x27.94mm"
  rrect50% 2.21x2.21 hole 1.6: 1(-10.16,10.16)
  round 2.21 hole 1.6: 2(-10.16,5.08) 3(-10.16,0) 4(-10.16,-5.08) 5(-10.16,-10.16) 6(10.16,-10.16) 7(10.16,-5.08) 8(10.16,0) 9(10.16,5.08) 10(10.16,10.16)
  silkscreen extent -14.74,-14.12 14.74,14.12, body extent -14.61,-13.97 14.6,13.97, height 21.59

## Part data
C1 C14 C38: library part CMP-0007044-5, "CAP, CERM, 0.1 uF, 50 V, +/- 10%, X7R, 0603", Cap_Case=0603, Manufacturer=TDK, Supplier Part Number 1=445-1314-1-ND, TempCo=X7R, Tolerance_%=10%, Value1="0.0296 ohm", Value2=50V, ValueDisplayed=0.1uF
C2: library part CMP-0007445-4, "CAP, CERM, 0.22 uF, 50 V, +/- 10%, X7R, 0603", Cap_Case=0603, Manufacturer=MuRata, Supplier Part Number 1=490-12546-1-ND, TempCo=X7R, Tolerance_%=10%, Value1=Unknown, Value2=50V, ValueDisplayed=0.22uF
C3 C4 C5 C6 C8 C9 C10 C11 C16 C17 C18 C19 C24: library part CMP-0009120-1, "CAP, CERM, 10 uF, 50 V, +/- 20%, X7R, 1210", Cap_Case=1210, Manufacturer=TDK, Supplier Part Number 1=445-14933-1-ND, TempCo=X7R, Tolerance_%=20%, Value1=Unknown, Value2=50V, ValueDisplayed=10uF
C7: library part CMP-0012273-1, "CAP, Aluminum Polymer, 180 uF, 50 V, +/- 20%, 0.019 ohm, SMD, 2-Leads, Dia 10.5mm, Pin Spacing 8mm SMD", Cap_Case=10x12.7mm, Manufacturer=Nichicon, Supplier Part Number 1=493-13774-1-ND, Tolerance_%=20%, Value1="0.019 ohm", Value2=50V, ValueDisplayed=180uF
C12 C21: library part CMP-0007097-4, "CAP, CERM, 0.47 uF, 50 V, +/- 10%, X7R, AEC-Q200 Grade 1, 0603", Cap_Case=0603, Manufacturer=TDK, Supplier Part Number 1=445-172475-1-ND, TempCo=X7R, Tolerance_%=10%, Value1=Unknown, Value2=50V, ValueDisplayed=0.47uF
C13 C28: library part CMP-0064933-4, "CAP, CERM, 1000 pF, 50 V,+/- 10%, X7R, 0603", Cap_Case=0603, Manufacturer="Wurth Elektronik", Supplier Part Number 1=732-8001-1-ND, TempCo=X7R, Tolerance_%=10%, Value1=Unknown, Value2=50V, ValueDisplayed=1000pF
C15: library part CMP-0079505-2, "CAP, Elko SMD, 330 µF, 35 V, +/- 20%, 0.080 ohm", Cap_Case=10x10.2mm, Manufacturer=Panasonic, PartNumber=EEHZC1V271V, Supplier Part Number 1=P19835CT-ND, Tolerance_%=20%, Value1="0.02 ohm", Value2=35V, ValueDisplayed=330µF
C20 C37: library part CMP-0007011-5, "CAP, CERM, 1 uF, 50 V, +/- 10%, X5R, 0603", Cap_Case=0603, Manufacturer=TDK, Supplier Part Number 1=445-7468-1-ND, TempCo=X5R, Tolerance_%=10%, Value1="0.005522 ohm", Value2=50V, ValueDisplayed=1uF
C22: library part CMP-0006858-4, "CAP, CERM, 0.1 uF, 50 V, +/- 5%, X7R, 0603", Cap_Case=0603, Manufacturer=Kemet, Supplier Part Number 1=399-7844-1-ND, TempCo=X7R, Tolerance_%=5%, Value1=Unknown, Value2=50V, ValueDisplayed=0.1uF
C23: library part CMP-0006924-4, "CAP, CERM, 0.33 uF, 16 V, +/- 10%, X7R, 0603", Cap_Case=0603, Manufacturer=Kemet, Supplier Part Number 1=399-4916-1-ND, TempCo=X7R, Tolerance_%=10%, Value1=Unknown, Value2=16V, ValueDisplayed=0.33uF
C25 C30: library part CMP-0007185-4, "CAP, CERM, 150 pF, 50 V, +/- 5%, C0G/NP0, 0603", Cap_Case=0603, Manufacturer=MuRata, Supplier Part Number 1=490-1431-1-ND, TempCo=C0G/NP0, Tolerance_%=5%, Value1=Unknown, Value2=50V, ValueDisplayed=150pF
C26 C27 C35 C36: library part CMP-0079602-1, "CAP, CERM, 0.1 µF, 50 V,+/- 10%, X7R, AEC-Q200 Grade 1, 0603", Cap_Case=0603, Manufacturer=Kemet, Supplier Part Number 1=399-6856-1-ND, TempCo=X7R, Tolerance_%=10%, Value2=50V, ValueDisplayed=0.1µF
C29 C34: library part CMP-0007405-2, "CAP, CERM, 1 uF, 25 V, +/- 10%, X7R, 0603", Cap_Case=0603, Manufacturer=MuRata, Supplier Part Number 1=490-5307-1-ND, TempCo=X7R, Tolerance_%=10%, Value1=Unknown, Value2=25V, ValueDisplayed=1uF
C31: library part CMP-0007185-4, Cap_Case=0603, Manufacturer=MuRata, TempCo=C0G/NP0, Tolerance_%=5%, Value1=Unknown, Value2=50V
C32: library part CMP-0006923-4, "CAP, CERM, 0.033 uF, 25 V, +/- 5%, X7R, 0603", Cap_Case=0603, Manufacturer=Kemet, Supplier Part Number 1=399-9068-1-ND, TempCo=X7R, Tolerance_%=5%, Value1=Unknown, Value2=25V, ValueDisplayed=0.033uF
C33: library part CMP-0007170-2, "CAP, CERM, 10 pF, 50 V, +/- 5%, C0G/NP0, 0603", Cap_Case=0603, Manufacturer=MuRata, Supplier Part Number 1=490-1403-1-ND, TempCo=C0G/NP0, Tolerance_%=5%, Value1=Unknown, Value2=50V, ValueDisplayed=10pF
D1 D2 D100: library part CMP-0028625-2, "Diode, Schottky, 100 V, 1 A, SOD-123FL", Manufacturer="ON Semiconductor", Value1=1A, Value2=0.76V
D3 D4: library part CMP-0028455-2, "Diode, Schottky, 30 V, 0.2 A, SOD-323", Manufacturer="ON Semiconductor", Value1=0.2A, Value2=0.35V
J1 J2: library part CMP-0055341-1, "Terminal Block, 3.5 mm, 2x1, Tin, TH", Manufacturer=Molex, Supplier Part Number 1=WM7877-ND
J3: library part CMP-0002338-1, "Header, 100mil, 3x1, Tin, TH", Color=Black, Current_A=3A, Manufacturer="Sullins Connector Solutions", Supplier Part Number 1=S1012E-03-ND, Voltage_V=1.8kV
L1 L2: library part CMP-0064047-1, "Inductor, Shielded Drum Core, Ferrite, 47 uH, 6.4 A, 0.033 ohm, SMD", Manufacturer="Wurth Elektronik", PartNumber=74435571100, Supplier Part Number 1=732-2175-1-ND, Value1="0.0069 ohm", Value2=16.5A, ValueDisplayed=47uH
L3 L5: library part CMP-0003159-1, "Ferrite Bead, 60 ohm @ 100 MHz, 6 A, 1806", Manufacturer="Wurth Elektronik", Supplier Part Number 1=732-1635-1-ND, Value1="0.01 ohm", Value2=6A, ValueDisplayed="60 ohm"
L4: library part CMP-0087242-1, "Shielded Power Inductors", Manufacturer=Coilcraft
L6: library part CMP-0087230-1, "COUPLED INDUCTOR"
NT1: library part CMP-0078142-1, "Single point connection between nets.", Manufacturer=N/A
Q1 Q2: library part CMP-0000915-1, "MOSFET, N-CH, 80 V, 100 A, DNK0008A (VSON-CLIP-8)", Alternate Manufacturer=None, Manufacturer="Texas Instruments", Supplier Part Number 1=296-37194-1-ND, Value2="48 nC"
Q3: library part CMP-0090577-1, "Bipolar (BJT) Transistor Array 2 PNP (Dual) Matched Pair 45V 100mA 175MHz 300mW Surface Mount 6-TSSOP", Collector Base Voltage=-50V, Digikey Part Number=1727-4883-1-ND, Emitter Base Voltage=-5V, Manufacturer=Nexperia, Mouser Part Number=771-BCM857BS115, Operating Temperature Range="to +150°C", Power_W=200mW, Unity Gain Freq=175MHz
R1: library part CMP-0025704-3, "RES, 10, 5%, 0.25 W, 0603", Manufacturer=Vishay-Dale, Power_W=250mW, Supplier Part Number 1=541-10SACT-ND, TempCo="200 ppm/C", Tolerance_%=5%, Value2=0.25W, Value_Code=10R0, ValueDisplayed=10
R2 R4 R33 R34 R100: library part CMP-0024594-3, "RES, 10.0, 0.5%, 0.1 W, 0603", Manufacturer="Yageo America", Power_W=100mW, TempCo="50 ppm/C", Tolerance_%=0.5%, Value2=0.1W, Value_Code=10R0, ValueDisplayed=10.0
R3 R10: library part CMP-0022448-2, "RES, 49.9, 1%, 0.1 W, 0603", Manufacturer=Vishay-Dale, Power_W=100mW, Supplier Part Number 1=541-49.9HCT-ND, TempCo="100 ppm/C", Tolerance_%=1%, Value2=0.1W, Value_Code=49R9, ValueDisplayed=49.9
R5: library part CMP-0016517-2, "RES, 0.025, 1%, 1 W, 2010", Manufacturer="Stackpole Electronics Inc", Power_W=1W, Supplier Part Number 1=CSRN2010FK25L0CT-ND, TempCo="250 ppm/C", Tolerance_%=1%, Value_Code=R025, ValueDisplayed=0.025
R6: library part CMP-0016971-3, "RES, 3.24, 1%, 0.25 W, AEC-Q200 Grade 0, 1206", Manufacturer=Vishay-Dale, Power_W=250mW, Supplier Part Number 1=541-3.24FFCT-ND, TempCo="100 ppm/C", Tolerance_%=1%, Value2=0.25W, Value_Code=3R24, ValueDisplayed=3.24
R7: library part CMP-0021936-2, "RES, 4.70, 1%, 0.125 W, 0805", Manufacturer="Yageo America", Power_W=125mW, Supplier Part Number 1=311-4.70CRCT-ND, TempCo="200 ppm/C", Tolerance_%=1%, Value2=0.125W, Value_Code=4R70, ValueDisplayed=4.70
R8: library part CMP-0016031-2, "RES, 0.007, 2%, 1 W, 2512", Manufacturer="Susumu Co Ltd", Power_W=1W, Supplier Part Number 1=KRL32C.007CT-ND, TempCo="100 ppm/C", Tolerance_%=2%, Value_Code=7L000, ValueDisplayed=0.007
R9: library part CMP-0025805-4, "RES, 3.3, 5%, 0.1 W, AEC-Q200 Grade 0, 0603", Manufacturer=Vishay-Dale, Power_W=100mW, Supplier Part Number 1=541-3.3GCT-ND, TempCo="200 ppm/C", Tolerance_%=5%, Value2=0.1W, Value_Code=3R30, ValueDisplayed=3.3
R11: library part CMP-0084355-1, "RES, 1.00 k, 0.5%, 0.1 W, 0603", Manufacturer=Yageo, Power_W=100mW, TempCo="25 ppm/C", Tolerance_%=0.5%, Value2=0.1W, Value_Code=1k00, ValueDisplayed=1.00k
R12: library part CMP-0022735-5, "RES, 100 k, 1%, 0.1 W, 0603", Manufacturer=Yageo, Power_W=100mW, Supplier Part Number 1=311-100KHRCT-ND, TempCo="100 ppm/C", Tolerance_%=1%, Value2=0.1W, Value_Code=100k
R13 R14: library part CMP-0022679-3, "RES, 100, 1%, 0.1 W, AEC-Q200 Grade 0, 0603", Manufacturer=Panasonic, Power_W=100mW, Supplier Part Number 1=P100HCT-ND, TempCo="100 ppm/C", Tolerance_%=1%, Value2=0.1W, Value_Code=100R, ValueDisplayed=100
R15: library part CMP-0022651-4, "RES, 90.9 k, 1%, 0.1 W, AEC-Q200 Grade 0, 0603", Manufacturer=Vishay-Dale, Power_W=100mW, Supplier Part Number 1=541-90.9KHCT-ND, TempCo="100 ppm/C", Tolerance_%=1%, Value2=0.1W, Value_Code=90k9, ValueDisplayed=90.9k
R16: library part CMP-0022000-4, "RES, 10.5 k, 1%, 0.1 W, AEC-Q200 Grade 0, 0603", Manufacturer=Vishay-Dale, Power_W=100mW, Supplier Part Number 1=541-10.5KHCT-ND, TempCo="100 ppm/C", Tolerance_%=1%, Value2=0.1W, Value_Code=10k5, ValueDisplayed=10.5k
R17: library part CMP-0022829-5, "RES, 16.5 k, 1%, 0.1 W, 0603", Manufacturer=Yageo, Power_W=100mW, Supplier Part Number 1=311-16.5KHRCT-ND, TempCo="100 ppm/C", Tolerance_%=1%, Value2=0.1W, Value_Code=16k5, ValueDisplayed=16.5k
R18: library part CMP-0022800-4, "RES, 147 k, 1%, 0.1 W, 0603", Manufacturer=Yageo, Power_W=100mW, Supplier Part Number 1=311-147KHRCT-ND, TempCo="100 ppm/C", Tolerance_%=1%, Value2=0.1W, Value_Code=147k
R19: library part CMP-0022632-4, "RES, 88.7 k, 1%, 0.1 W, AEC-Q200 Grade 0, 0603", Manufacturer=Vishay-Dale, Power_W=100mW, Supplier Part Number 1=541-88.7KHCT-ND, TempCo="100 ppm/C", Tolerance_%=1%, Value2=0.1W, Value_Code=88k7, ValueDisplayed=88.7k
R20: library part CMP-0023239-5, "RES, 68.0 k, 1%, 0.1 W, 0603", Manufacturer=Yageo, Power_W=100mW, Supplier Part Number 1=311-68.0KHRCT-ND, TempCo="100 ppm/C", Tolerance_%=1%, Value2=0.1W, Value_Code=68k0, ValueDisplayed=68.0k
R21 R23 R29 R31: library part CMP-0021998-4, "RES, 10.0 k, 1%, 0.1 W, AEC-Q200 Grade 0, 0603", Manufacturer=Vishay-Dale, Power_W=100mW, Supplier Part Number 1=541-10.0KHCT-ND, TempCo="100 ppm/C", Tolerance_%=1%, Value2=0.1W, Value_Code=10k0, ValueDisplayed=10.0k
R22 R30: library part CMP-0065390-2, "Potentiometer, 100k Ohm, 0.5W, TH", Manufacturer=Bourns, Supplier Part Number 1=490-2876-ND
R24: library part CMP-0080488-1, "RES, 10.0 k, 1%, 0.1 W, 0603", Manufacturer="TT Electronics/IRC", Power_W=100mW, TempCo="100 ppm/C", Tolerance_%=1%, Value2=0.1W, Value_Code=10k0, ValueDisplayed=10.0k
R25: library part CMP-0022895-5, "RES, 1.00 k, 1%, 0.1 W, 0603", Manufacturer=Yageo, Power_W=100mW, Supplier Part Number 1=311-1.00KHRCT-ND, TempCo="100 ppm/C", Tolerance_%=1%, Value2=0.1W, Value_Code=1k00, ValueDisplayed=1.00k
R26: library part CMP-0022986-5, "RES, 2.20 k, 1%, 0.1 W, 0603", Manufacturer=Yageo, Power_W=100mW, Supplier Part Number 1=311-2.20KHRCT-ND, TempCo="100 ppm/C", Tolerance_%=1%, Value2=0.1W, Value_Code=2k20, ValueDisplayed=2.20k
R27: library part CMP-0022906-5, "RES, 20.0 k, 1%, 0.1 W, 0603", Manufacturer=Yageo, Power_W=100mW, Supplier Part Number 1=311-20.0KHRCT-ND, TempCo="100 ppm/C", Tolerance_%=1%, Value2=0.1W, Value_Code=20k0, ValueDisplayed=20.0k
R28: library part CMP-0025697-4, "RES, 0, 5%, 0.1 W, AEC-Q200 Grade 0, 0603", Manufacturer=Vishay-Dale, Power_W=100mW, Supplier Part Number 1=541-0.0GCT-ND, TempCo="200 ppm/C", Tolerance_%=5%, Value2=0.1W, Value_Code=0000, ValueDisplayed=0
R32: library part CMP-0022635-3, "RES, 8.25 k, 1%, 0.1 W, 0603", Manufacturer=Vishay-Dale, Power_W=100mW, Supplier Part Number 1=541-8.25KHCT-ND, TempCo="100 ppm/C", Tolerance_%=1%, Value2=0.1W, Value_Code=8k25, ValueDisplayed=8.25k
TP1 TP4 TP6 TP7 TP15: library part CMP-0055147-1, "Test Point, Multipurpose, Red, TH", Color=Red, Manufacturer=Keystone, Supplier Part Number 1=36-5010-ND
TP2 TP5 TP10: library part CMP-0055151-1, "Test Point, Multipurpose, Yellow, TH", Color=Yellow, Manufacturer=Keystone, Supplier Part Number 1=36-5014-ND
TP3 TP8 TP9 TP11 TP13: library part CMP-0055148-1, "Test Point, Multipurpose, Black, TH", Color=Black, Manufacturer=Keystone, Supplier Part Number 1=36-5011-ND
TP12 TP14: library part CMP-0055137-1, "Test Point, Miniature, Red, TH", Color=Red, Manufacturer=Keystone, Supplier Part Number 1=36-5000-ND
U1: library part CMP-0750214-2, "INA293 High-Voltage, High Bandwidth, Unidirectional, 110-V Common-Mode, Current-Sense Amplifier, DBV0005A (SOT-23-5)", Alternate Manufacturer="Texas Instruments", Alternate PartNumber=INA293A2IDBVT
U2: library part CMP-0066110-3, "3-65V Wide Vin, Current Mode Synchronous Boost Controller with Multiphase Capability, PWP0020A (HTSSOP-20)", Alternate Manufacturer="Texas Instruments", Alternate PartNumber=LM5122MHE/NOPB, Operating Temperature Range="-40 to 125 C", Rating=Catalog
U3: library part CMP-0043404-1, "LinCMOS(TM) Precision Dual Operational Amplifier, 4 to 16 V, -40 to 85 degC, 8-pin SOIC (D8), Green (RoHS & no Sb/Br)", Manufacturer="Texas Instruments", Rating=Catalog, Total Supply Voltage(Max)(+5V is 5, +/-5V is 10)=16, Total Supply Voltage(Min)(+5V is 5, +/-5V is 10)=4
U4: library part CMP-0033039-1, "Precision Micropower Shunt Voltage Reference, 1% accuracy, 3 V, 15 ppm / degC, 15 mA, -40 to 85 degC, 3-pin SOT-23 (DBZ), Green (RoHS & no Sb/Br)", Manufacturer="Texas Instruments", Rating=Catalog, Temp Coeff(Max)(ppm/ degree C)=150, Temp Coeff(Typ)(ppm/ degree C)=15

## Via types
v1: diameter 0.864, hole 0.406, Top Layer to Bottom Layer, 59 vias
v2: diameter 1.016, hole 0.508, Top Layer to Bottom Layer, 39 vias
v3: diameter 1.016, hole 0.508, Top Layer to Bottom Layer, tented top, 15 vias
v4: diameter 0.864, hole 0.406, Top Layer to Bottom Layer, tented top, 11 vias
v5: diameter 0.5, hole 0.2, Top Layer to Bottom Layer, 9 vias
v6: diameter 0.5, hole 0.2, Top Layer to Bottom Layer, tented both sides, 6 vias

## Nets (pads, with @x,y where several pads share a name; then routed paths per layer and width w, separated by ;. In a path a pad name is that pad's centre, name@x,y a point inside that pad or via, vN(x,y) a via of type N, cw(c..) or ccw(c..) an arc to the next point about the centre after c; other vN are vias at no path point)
AGND: C1.2 C22.2 C23.2 C27.1 C28.2 C29.2 C33.2 C34.2 C35.2 C36.1 J3.3 NT1.1 R16.1 R17.1 R18.1 R19.1 R22.3 R25.1 R30.1 TP3.1 TP8.1 TP13.1 U1.2 U2.2 U2.9 U3.4 U4.2 | length 40.4
  Top Layer w0.381: v4(43.763,15.715) 43.763,15.846 44.036,16.119 U2.2@44.036,17.337 ; U2.9@48.586,17.337 48.586,16.118 48.851,15.853 v4(48.851,15.723)
  Top Layer w0.7: v4(48.851,15.723) 48.851,15.679 49.53,14.999 49.53,14.478
  Layer 1 w0.508: J3.3@10.997,15.969 24.318,15.969 27.587,12.7 40.748,12.7 v4(43.763,15.715)
  other v1: 70.56,3.672 77.724,3.81 78.74,3.81 78.232,4.572 58.166,4.826 59.436,4.826 60.706,4.826 61.976,4.826 67.818,6.858 69.342,6.858 70.612,6.858 86.106,7.112 57.658,7.366 48.387,7.62 50.546,7.62 52.578,7.62 67.928,8.11 69.342,8.128 86.106,8.382 54.102,9.144 57.658,11.938 60.96,14.732 71.628,15.748 60.96,16.002 71.628,16.764 52.07,18.288 53.34,18.288 54.61,18.288 54.61,19.558 54.61,20.574 54.61,21.59 55.245,23.876 68.072,24.892 69.088,24.892 70.104,24.892 71.12,24.892 55.245,25.019 55.245,26.162
  other v4: 86.106,5.842 70.866,14.732 73.26,27.399
COMP: C30.2 R27.1 U2.11 | length 6.2
  Top Layer w0.381: U2.11@49.255,23.335 49.255,23.172 49.27,23.157 49.834,23.157 51.002,21.989 51.002,21.112 C30.2@51.002,21.087 R27.1@52.907,21.087 ; U2.11@49.27,22.728 49.236,22.762 U2.11@49.236,23.237 49.236,23.663 U2.11@49.27,23.697
"Current Loop": C33.1 R3.1 R29.1 TP2.1 | length 14
  Top Layer w0.508: R3.1@78.307,16.32 78.39,16.403 81.399,16.403 TP2.1@81.482,16.485 84.657,13.31 R29.1@84.657,9.83 84.676,9.849 87.432,9.849 C33.1@87.451,9.868
FB: C30.1 R24.2 R27.2 U2.10 | length 11.1
  Top Layer w0.381: U2.10@49.27,16.828 49.236,16.862 U2.10@49.236,17.337 ; U2.10@49.27,17.847 49.236,17.812 U2.10@49.236,17.337 ; C30.1@50.717,19.487 R27.2@52.907,19.487 ; C30.1@51.002,19.487 50.773,19.258 50.773,18.661 50.094,17.982 50.094,17.272 ; R24.2@51.886,13.683 51.861,13.683 51.576,13.968 51.576,14.252 50.094,15.734 50.094,17.272 ; U2.10@49.236,17.337 50.029,17.337 50.094,17.272
GND: C8.2 C9.2 C10.2 C11.2 C12.2 C14.2 C15.2 C16.2 C17.2 C18.2 C19.2 C24.1 C37.2 C38.2 J1.2 J2.1 NT1.2 Q2.1 Q2.2 Q2.3 R4.1 R5.1 TP9.1 TP11.1 U2.15 U2.21@46.311,20.287 | length 38.9
  Top Layer w0.45: U2.21@46.636,21.612 U2.15@46.636,23.237
  Top Layer w0.508: C14.2@9.689,53.053 9.689,57.079 J1.2@12.394,59.784 ; v5(46.311,21.287) U2.21@46.636,21.612 ; v1(77.291,49.243) 77.291,51.261 R5.1@77.559,51.529 ; R4.1@78.359,32.423 78.359,33.559 78.486,33.686 v1(78.486,33.782) ; C37.2@88.505,52.291 C38.2@88.505,54.069 88.505,58.58 J2.1@89.709,59.784 ; TP9.1@96.622,60.927 TP9.1@96.976,60.927
  Layer 1 w0.508: v1(77.291,49.243) 76.275,48.227 76.275,35.993 v1(78.486,33.782)
  other v1: 44.246,9.327
  other v2: 5.715,27.94 7.62,27.94 5.715,29.845 7.62,29.845 5.715,31.75 7.62,31.75 37.465,31.75 38.735,31.75 40.005,31.75 41.275,31.75 37.465,33.02 38.735,33.02 40.005,33.02 41.275,33.02 5.715,33.655 7.62,33.655 5.715,35.56 7.62,35.56 5.715,37.465 7.62,37.465 5.715,40.005 7.62,40.005 93.98,42.545 97.79,42.545 93.98,43.815 97.79,43.815 93.98,45.085 97.79,45.085 93.98,46.355 97.79,46.355 79.375,50.8 79.375,52.07 80.645,52.07 76.835,53.975 78.74,53.975 80.645,53.975 76.835,55.245 78.74,55.245 80.645,55.245
  other v3: 61.214,42.672 62.865,42.672 64.77,42.672 66.675,42.672 68.58,42.672 70.485,42.672 72.39,42.672 74.295,42.672 62.865,43.942 64.77,43.942 66.675,43.942 68.58,43.942 70.485,43.942 72.39,43.942 74.295,43.942
  other v5: 45.011,19.287 46.311,19.287 47.611,19.287 45.011,20.287 46.311,20.287 47.611,20.287 45.011,21.287 47.611,21.287
  other v6: 43.711,19.287 48.911,19.287 43.711,20.287 48.911,20.287 43.711,21.287 48.911,21.287
NetC1_1: C1.1 R1.1 U1.5 | length 4.3
  Top Layer w0.508: R1.1@68.401,27.945 68.464,28.009 70.275,28.009 C1.1@70.339,28.072 71.833,28.072 72.31,28.549 U1.5@72.31,28.674
NetC2_1: C2.1 R2.2 U1.4 | length 4.7
  Top Layer w0.508: U1.4@74.21,28.674 74.21,28.629 74.231,28.608 v4(75.344,28.608) 76.458,28.608 C2.1@76.489,28.577 ; R2.2@76.454,30.823 76.489,30.788 C2.1@76.489,28.577 ; C2.1@76.524,28.542 C2.1@76.489,28.577
NetC2_2: C2.2 R4.2 U1.3 | length 8.7
  Top Layer w0.508: U1.3@74.21,26.124 77.464,26.124 78.028,26.688 78.028,28.611 C2.2@78.041,28.624 ; C2.2@78.124,28.542 78.188,28.606 78.188,29.927 78.36,30.099 R4.2@78.359,30.823 ; R4.2@78.124,30.563 78.359,30.798 R4.2@78.359,30.823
